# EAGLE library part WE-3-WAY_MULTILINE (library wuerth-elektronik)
Multiline EMI Suppression Ferrite - Filter for common mode or differential mode - High rated current with typ. 4 A -- Perfect suitable for absorption of common or differential mode interferences in the field of EMC -- High current DC output filters of power supplies e.g. battery chargers, industrial power supplies
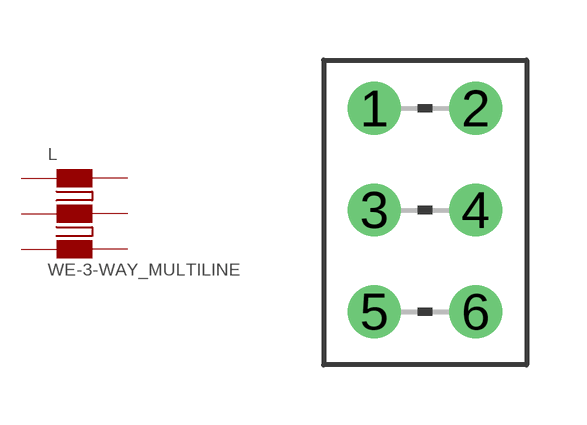
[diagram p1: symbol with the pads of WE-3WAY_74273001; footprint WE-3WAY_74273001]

Designator prefix L

## WE-3-WAY_MULTILINE  [WE-3WAY_74273001]
1  1  pas
2  2  pas
3  3  pas
4  4  pas
5  5  pas
6  6  pas

## Footprint WE-3WAY_74273001 (pad centres in mm)
Multiline Ferrite 3-way
drill 0.813 round: 1 -1.27,2.54; 2 1.27,2.54; 3 -1.27,0; 4 1.27,0; 5 -1.27,-2.54; 6 1.27,-2.54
